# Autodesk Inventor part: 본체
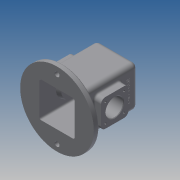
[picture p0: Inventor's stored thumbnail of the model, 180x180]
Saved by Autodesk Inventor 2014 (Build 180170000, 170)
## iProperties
Created: 2021-08
Part Number: 본체
Material: Generic
Document SubType Name: Modeling
Designer: kb542
Density: 1 g/cm^3
Appearance: Default
Mass: 304.336 g
Surface Area: 949.017 cm^2
Volume: 304.336 cm^3
Author: kb542
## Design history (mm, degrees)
sketch "스케치1"
  geometry: L1 (37, 37)-(-37, 37); L2 (-37, 37)-(-37, -37); L3 (-37, -37)-(37, -37); L4 (37, -37)-(37, 37); L5 (37, 37)-(-37, -37); L6 (-37, 37)-(37, -37); 1 further point
  constraints: 12 end point, 2 midpoint, 2 parallel, 1 horizontal, 1 perpendicular
  dimensions: "d1" = 74 distance of L2.end L3.end; "d2" = 74 distance of L1.end L2.end
extrude "돌출1" new body sketch "스케치1" distance "d3" = 100; taper "d4" = 0 deg
feature "쉘1" dims "d5" = 5
sketch "스케치2"
  geometry: L1 (-32, -32)-(-32, 32) reference; L2 (-32, 32)-(32, 32) reference; L3 (32, 32)-(32, -32) reference; L4 (32, -32)-(-32, -32) reference; C1 r 67 at (0, 0); 1 further point
  constraints: 1 centre point, 1 coincident
  dimensions: "d6" = 134 diameter of C1
extrude "돌출2" join sketch "스케치2" distance "d7" = 10; taper "d8" = 0 deg
node "작업 평면1"
sketch "스케치3"
  geometry: C1 r 20 at (0, 0); 2 further points
  constraints: 2 coincident, 1 centre point
  dimensions: "d10" = 40 diameter of C1
extrude "돌출3" join sketch "스케치3" stored distance "d11" = 10; taper "d12" = 6 deg
hole "구멍1" sketch "스케치3" diameter "d13" = 21; stored, may be unused: countersink angle "d17" = 90 deg, drill point angle "d19" = 118 deg; dims "d14" = 6, "d15" = 28, "d16" = 4, "d18" = 8
sketch "스케치4"
  geometry: C1 r 67 at (0, 0) reference; A1 r 55 centre (0, 0) between (0, 55) and (0, -55)
  constraints: 2 point on circle, 2 vertical alignment, 1 centre point, 1 coincident
  dimensions: "d20" = 110 diameter of A1
hole "구멍2" sketch "스케치4" at (0, 55), (0, -55) diameter "d21" = 9; stored, may be unused: countersink angle "d25" = 90 deg, drill point angle "d27" = 118 deg; dims "d22" = 6, "d23" = 28, "d24" = 4, "d26" = 8
node "작업 평면2"
sketch "스케치5"
  geometry: L1 (12, -80)-(62, -80); L2 (62, -80)-(62, -30); L3 (62, -30)-(12, -30); L4 (12, -30)-(12, -80); L5 (12, -80)-(62, -30); L6 (62, -80)-(12, -30); L7 (-30, -110)-(104, -110) reference; L8 (20, -72)-(54, -72); L9 (54, -72)-(54, -38); L10 (54, -38)-(20, -38); L11 (20, -38)-(20, -72); L12 (20, -72)-(54, -38); L13 (54, -72)-(20, -38); C1 r 16 at (37, -55); 7 further points
  constraints: 24 end point, 7 midpoint, 4 coincident, 4 parallel, 2 horizontal, 2 perpendicular, 1 centre point, 1 point on line, 1 vertical alignment
  dimensions: "d29" = 50 distance of L2.end L3.end; "d30" = 50 distance of L1.end L2.end; "d31" = 55 distance from line of L7 point (37, -55); "d32" = 34 distance of L9.end L10.end; "d33" = 32 diameter of C1
extrude "돌출4" join sketch "스케치5" stored distance "d34" = 10; taper "d35" = 0 deg
hole "구멍3" sketch "스케치5" diameter "d36" = 3.242; stored, may be unused: countersink angle "d40" = 90 deg, drill point angle "d42" = 118 deg; dims "d37" = 8, "d38" = 28, "d39" = 4, "d41" = 10
extrude "돌출7" cut sketch "스케치5" stored distance "d48" = 10; taper "d49" = 0 deg
node "작업축1"
sketch "스케치7"
  geometry: L1 (93.8, 45)-(-93.8, 45) reference; L2 (-37, 20)-(-50, 20) reference; L3 (-50, 20)-(-50, 29) reference; L4 (-50, 29)-(-32, 29) reference; L5 (-32, 29)-(-32, -10) reference; L6 (-32, -10)-(-67, -10) reference; L7 (-67, -10)-(-67, 0) reference; L8 (-67, 0)-(-37, 0) reference; L9 (-37, 0)-(-37, 20) reference; L10 (20, 110)-(21.051, 100) reference; L11 (21.051, 100)-(37, 100) reference; L12 (37, 100)-(37, 70) reference; L13 (37, 70)-(50, 70) reference; L14 (50, 70)-(50, 61) reference; L15 (50, 61)-(32, 61) reference; L16 (32, 61)-(32, 95) reference; L17 (32, 95)-(10.5, 95) reference; L18 (10.5, 95)-(10.5, 106) reference; L19 (10.5, 106)-(14, 106) reference; L20 (14, 106)-(14, 110) reference; L21 (14, 110)-(20, 110) reference; L22 (-21.051, 100)-(-20, 110) reference; L23 (-20, 110)-(-14, 110) reference; L24 (-14, 110)-(-14, 106) reference; L25 (-14, 106)-(-10.5, 106) reference; L26 (-10.5, 106)-(-10.5, 95) reference; L27 (-10.5, 95)-(-32, 95) reference; L28 (-32, 95)-(-32, 61) reference; L29 (-32, 61)-(-50, 61) reference; L30 (-50, 61)-(-50, 70) reference; L31 (-50, 70)-(-37, 70) reference; L32 (-37, 70)-(-37, 100) reference; L33 (-37, 100)-(-21.051, 100) reference; L34 (37, 0)-(67, 0) reference; L35 (67, 0)-(67, -10) reference; L36 (67, -10)-(32, -10) reference; L37 (32, -10)-(32, 29) reference; L38 (32, 29)-(50, 29) reference; L39 (50, 29)-(50, 20) reference; L40 (50, 20)-(37, 20) reference; L41 (37, 20)-(37, 0) reference; L42 (-32, 45)-(-25, 45); L43 (-25, 45)-(-25, 22.548); L44 (-32, 20)-(-32, 45); L45 (-32, 20)-(-25, 22.548); 1 further point
  constraints: 8 end point, 1 collinear, 1 horizontal, 1 parallel, 1 perpendicular, 1 point on line
  dimensions: "d50" = 50 diameter of L44.start L1; "d51" = 7 distance between parallel lines of L44 L43; "d52" = 110 deg angle of L5 L45
revolve "회전1" sketch "스케치7" stored, may be unused: angle "d53" = 90 deg
sketch "스케치8"
  geometry: C1 r 16 at (0, 0) reference; 1 further point
extrude "돌출8" cut sketch "스케치8" stored distance "d54" = 10; taper "d55" = 0 deg
sketch "스케치9"
  geometry: L1 (0, -100)-(0, 0) reference; L2 (17, 10)-(57, 10) reference; 2 further points
  constraints: 1 other
  dimensions: "d56" = 37 distance from line of point (37, -18) L1; "d57" = 28 distance from line of point (37, -18) L2
feature "엠보싱1" sketch "스케치9" dims "d1" = 74, "d2" = 74, "d58" = 0.5, "d59" = 0
fillet "모깎기1" dims "d60" = 8
fillet "모깎기2" dims "d61" = 8
fillet "모깎기3" dims "d62" = 8
fillet "모깎기4" dims "d63" = 3
fillet "모깎기5" dims "d64" = 3
fillet "모깎기6" dims "d65" = 3
fillet "모깎기7" dims "d66" = 3
chamfer "모따기1" distance "d67" = 1; stored, may be unused: second distance "d68" = 2, angle "d69" = 45 deg
node "솔리드1"
mirror "대칭1"
mirror "대칭2"
node "절단 모서리 투영1"
other parameters: "d28" = 13
